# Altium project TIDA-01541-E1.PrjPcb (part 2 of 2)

## Sheet TIDA-01541-E1_MCU Interface.SchDoc: MCU Interface
size 431 x 279 mm; Date: Not shown in title block; ApprovedBy: Not shown in title block; CheckedBy: Not shown in title block; Author: Not shown in title block; CompanyName: Not shown in title block; DrawnBy: NN; Engineer: Not shown in title block; Organization: Not shown in title block; Address1: Not shown in title block; Address2: Not shown in title block; Address3: Not shown in title block; Address4: Not shown in title block; DocumentNumber: 1; Revision: Use project parameter SCH_Rev; SheetNumber: 5; SheetTotal: 6; PageSetup: Record=PageOptions¦CenterHorizontal=True¦CenterVertical=True¦PrintScale=1.00¦XCorrection=1.00¦YCorrection=1.00¦PrintKind=0¦BorderSize=5000000¦LeftOffset=0¦BottomOffset=0¦Orientation=2¦PaperLength=1000¦PaperWidth=1000¦Scale=100¦PaperSource=15¦PrintQuality=600¦MediaType=1¦DitherType=10¦PaperKind=Letter¦PrintScaleMode=1
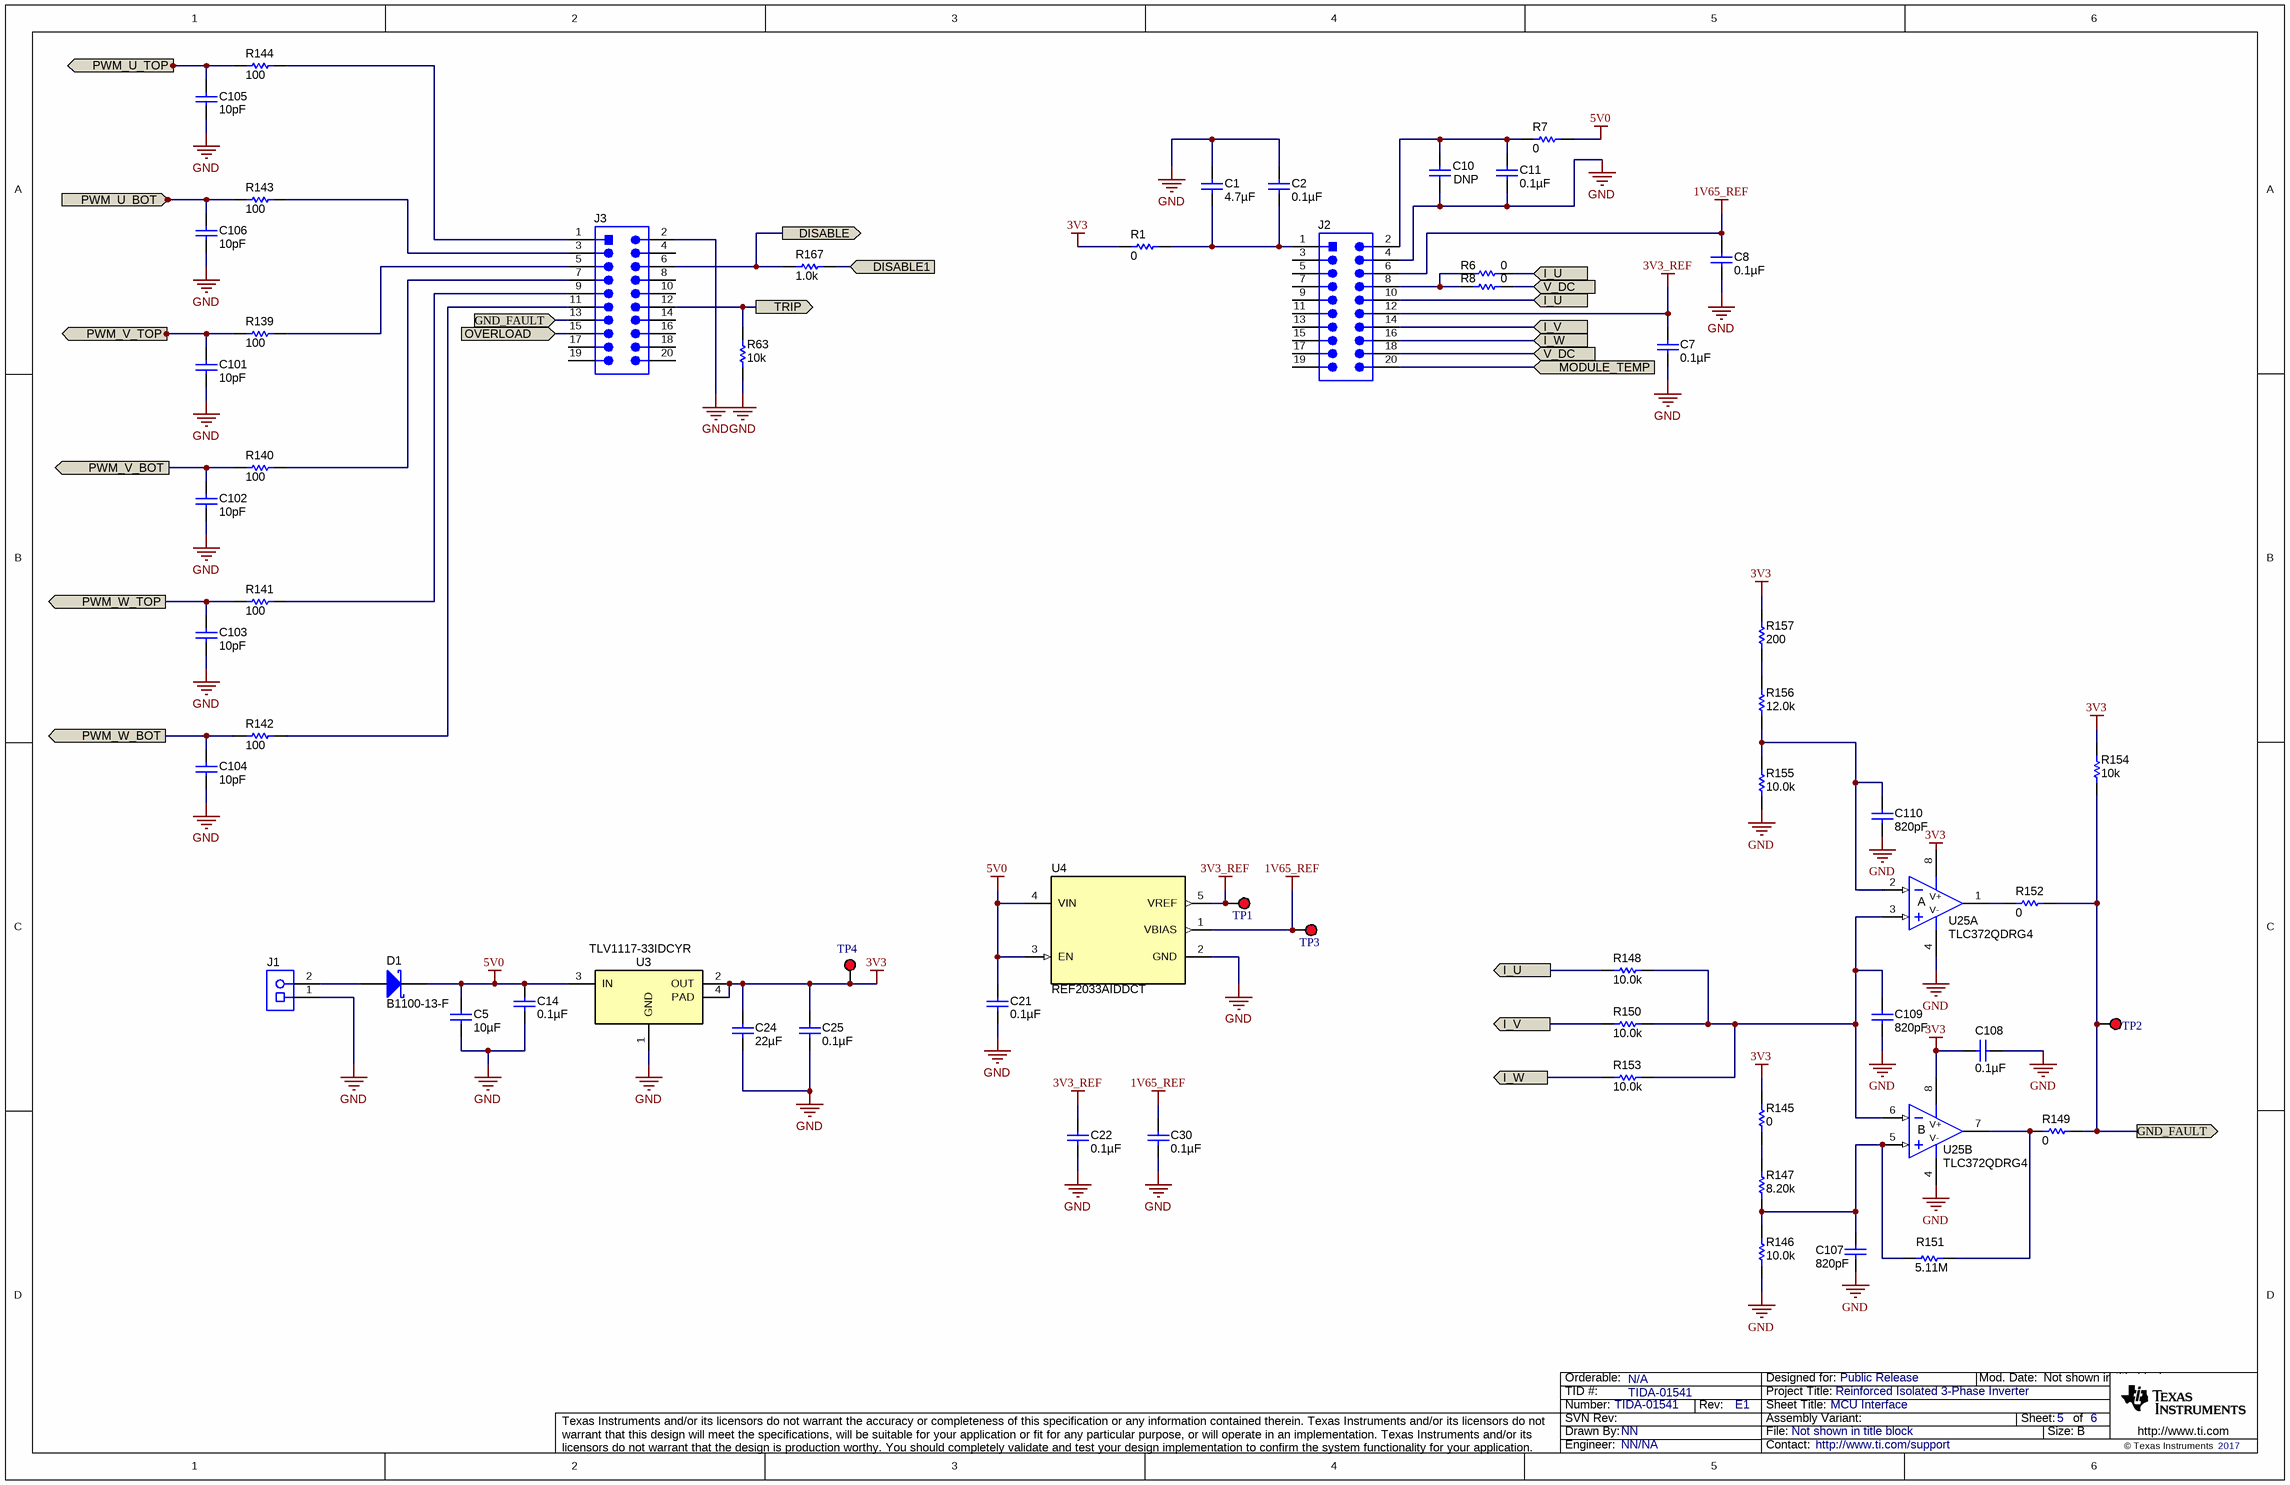
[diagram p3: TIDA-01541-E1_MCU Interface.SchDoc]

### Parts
C1  ValueDisplayed: 4.7µF  [0805_HV]  (hidden comment: C2012X5R1H475K125AB)
C2  ValueDisplayed: 0.1µF  [0603]  (hidden comment: GRM188R71H104KA93D)
C5  ValueDisplayed: 10µF  [1210_280]  (hidden comment: C3225X5R1H106K250AB)
C7  ValueDisplayed: 0.1µF  [0603]  (hidden comment: GRM188R71H104KA93D)
C8  ValueDisplayed: 0.1µF  [0603]  (hidden comment: GRM188R71H104KA93D)
C10  C2012X5R1H475K125AB  [0805_HV]  (value not drawn)
C11  ValueDisplayed: 0.1µF  [0603]  (hidden comment: GRM188R71H104KA93D)
C14  ValueDisplayed: 0.1µF  [0603]  (hidden comment: GRM188R71H104KA93D)
C21  ValueDisplayed: 0.1µF  [0603]  (hidden comment: GRM188R71H104KA93D)
C22  ValueDisplayed: 0.1µF  [0603]  (hidden comment: GRM188R71H104KA93D)
C24  ValueDisplayed: 22µF  [0805_HV]  (hidden comment: CL21A226MAQNNNE)
C25  ValueDisplayed: 0.1µF  [0603]  (hidden comment: GRM188R71H104KA93D)
C30  ValueDisplayed: 0.1µF  [0603]  (hidden comment: GRM188R71H104KA93D)
C101  ValueDisplayed: 10pF  [0603]  (hidden comment: GRM1885C1H100JA01D)
C102  ValueDisplayed: 10pF  [0603]  (hidden comment: GRM1885C1H100JA01D)
C103  ValueDisplayed: 10pF  [0603]  (hidden comment: GRM1885C1H100JA01D)
C104  ValueDisplayed: 10pF  [0603]  (hidden comment: GRM1885C1H100JA01D)
C105  ValueDisplayed: 10pF  [0603]  (hidden comment: GRM1885C1H100JA01D)
C106  ValueDisplayed: 10pF  [0603]  (hidden comment: GRM1885C1H100JA01D)
C107  ValueDisplayed: 820pF  [0603]  (hidden comment: GRM188R71H821KA01D)
C108  ValueDisplayed: 0.1µF  [0603]  (hidden comment: GRM188R71H104KA93D)
C109  ValueDisplayed: 820pF  [0603]  (hidden comment: GRM188R71H821KA01D)
C110  ValueDisplayed: 820pF  [0603]  (hidden comment: GRM188R71H821KA01D)
D1  B1100-13-F  [SMA]
J1  282834-2  [TEC_282834-2]  (value not drawn)
J2  TSW-110-07-G-D  [TSW-110-07-G-D]  (value not drawn)
J3  TSW-110-07-G-D  [TSW-110-07-G-D]  (value not drawn)
R1  ValueDisplayed: 0  [0805_HV]  (hidden comment: ERJ-6GEY0R00V)
R6  ValueDisplayed: 0  [0603]  (hidden comment: ERJ-3GEY0R00V)
R7  ValueDisplayed: 0  [0805_HV]  (hidden comment: ERJ-6GEY0R00V)
R8  ValueDisplayed: 0  [0603]  (hidden comment: ERJ-3GEY0R00V)
R63  ValueDisplayed: 10k  [0603]  (hidden comment: RC0603JR-0710KL)
R139  ValueDisplayed: 100  [0603]  (hidden comment: RC0603FR-07100RL)
R140  ValueDisplayed: 100  [0603]  (hidden comment: RC0603FR-07100RL)
R141  ValueDisplayed: 100  [0603]  (hidden comment: RC0603FR-07100RL)
R142  ValueDisplayed: 100  [0603]  (hidden comment: RC0603FR-07100RL)
R143  ValueDisplayed: 100  [0603]  (hidden comment: RC0603FR-07100RL)
R144  ValueDisplayed: 100  [0603]  (hidden comment: RC0603FR-07100RL)
R145  ValueDisplayed: 0  [0603]  (hidden comment: ERJ-3GEY0R00V)
R146  ValueDisplayed: 10.0k  [0603]  (hidden comment: PHT0603Y1002BGT200)
R147  ValueDisplayed: 8.20k  [0603]  (hidden comment: RG1608P-822-B-T5)
R148  ValueDisplayed: 10.0k  [0603]  (hidden comment: PHT0603Y1002BGT200)
R149  ValueDisplayed: 0  [0603]  (hidden comment: ERJ-3GEY0R00V)
R150  ValueDisplayed: 10.0k  [0603]  (hidden comment: PHT0603Y1002BGT200)
R151  ValueDisplayed: 5.11M  [0603]  (hidden comment: CRCW06035M11FKEA)
R152  ValueDisplayed: 0  [0603]  (hidden comment: ERJ-3GEY0R00V)
R153  ValueDisplayed: 10.0k  [0603]  (hidden comment: PHT0603Y1002BGT200)
R154  ValueDisplayed: 10k  [0603]  (hidden comment: RC0603JR-0710KL)
R155  ValueDisplayed: 10.0k  [0603]  (hidden comment: PHT0603Y1002BGT200)
R156  ValueDisplayed: 12.0k  [0603]  (hidden comment: RG1608P-123-B-T5)
R157  ValueDisplayed: 200  [0603]  (hidden comment: RG1608P-201-B-T5)
R167  ValueDisplayed: 1.0k  [0603]  (hidden comment: RC0603JR-071KL)
TP1  5000  [Keystone5000]  (value not drawn)
TP2  5000  [Keystone5000]  (value not drawn)
TP3  5000  [Keystone5000]  (value not drawn)
TP4  5000  [Keystone5000]  (value not drawn)
U3  TLV1117-33IDCYR  [DCY0003A_N]
U4  REF2033AIDDCT  [DDC0005A_N]
U25  TLC372QDRG4  [D0008A_N]  (parts A,B of 2)

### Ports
DISABLE1 (in), DISABLE (out), GND_FAULT (in), GND_FAULT (out), I_U, I_U (in), I_V, I_V (in), I_W, I_W (in), MODULE_TEMP (in), OVERLOAD (in), PWM_U_BOT (out), PWM_U_TOP (out), PWM_V_BOT (out), PWM_V_TOP (out), PWM_W_BOT (out), PWM_W_TOP (out), TRIP (out), V_DC (in)

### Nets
1V65_REF: C8.1 C30.1 J2.6 TP3.1 U4.1(VBIAS)
3V3: C24.1 C25.1 C108.2 R1.1 R145.1 R154.2 R157.1 TP4.1 U3.2(OUT) U3.4(PAD) U25.8(V+)
3V3_REF: C7.1 C22.1 J2.12 TP1.1 U4.5(VREF)
5V0: C5.1 C14.1 C21.1 D1.1(K) R7.2 U3.3(IN) U4.3(EN) U4.4(VIN)
GND: C1.1 C2.1 C5.2 C7.2 C8.2 C10.2 C11.2 C14.2 C21.2 C22.2 C24.2 C25.2 C30.2 C101.2 C102.2 C103.2 C104.2 C105.2 C106.2 C107.1 C108.1 C109.1 C110.1 J1.1 J2.4 J3.2 R63.1 R146.2 R155.2 U3.1(GND) U4.2(GND) U25.4(V-)
DISABLE: J3.6 R167.2 ; port DISABLE
DISABLE1: R167.1 ; port DISABLE1
GND_FAULT: J3.13 R149.2 R152.2 R154.1 TP2.1 ; port GND_FAULT
I_U: J2.10 R6.2 R148.1 ; port I_U
I_V: J2.14 R150.1 ; port I_V
I_W: J2.16 R153.1 ; port I_W
MODULE_TEMP: J2.20 ; port MODULE_TEMP
OVERLOAD: J3.15 ; port OVERLOAD
PWM_U_BOT: C106.1 R143.1 ; port PWM_U_BOT
PWM_U_TOP: C105.1 R144.1 ; port PWM_U_TOP
PWM_V_BOT: C102.1 R140.1 ; port PWM_V_BOT
PWM_V_TOP: C101.1 R139.1 ; port PWM_V_TOP
PWM_W_BOT: C104.1 R142.1 ; port PWM_W_BOT
PWM_W_TOP: C103.1 R141.1 ; port PWM_W_TOP
TRIP: J3.12 R63.2 ; port TRIP
V_DC: J2.18 R8.2 ; port V_DC
NetC1_2: C1.2 C2.2 J2.1 R1.2
NetC10_1: C10.1 C11.1 J2.2 R7.1
NetC107_2: C107.2 R146.1 R147.2 R151.1 U25.5(IN+)
NetC109_2: C109.2 R148.2 R150.2 R153.2 U25.3(IN+) U25.6(IN-)
NetC110_2: C110.2 R155.1 R156.2 U25.2(IN-)
NetD1_2: D1.2(A) J1.2
NetJ2_8: J2.8 R6.1 R8.1
NetJ3_1: J3.1 R144.2
NetJ3_3: J3.3 R143.2
NetJ3_5: J3.5 R139.2
NetJ3_7: J3.7 R140.2
NetJ3_9: J3.9 R141.2
NetJ3_11: J3.11 R142.2
NetR145_2: R145.2 R147.1
NetR149_1: R149.1 R151.2 U25.7(OUT)
NetR152_1: R152.1 U25.1(OUT)
NetR156_1: R156.1 R157.2

Not connected (* = marked no-connect by the designer): J2 3 5 7 9 11 13 15 17 19; J3 4 8 10 14 16 17 18 19 20

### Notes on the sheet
- Labels drawn without touching a wire or pin: 3V3

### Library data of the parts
C1 = C2012X5R1H475K125AB: CAP, CERM, 4.7 µF, 50 V, +/- 10%, X5R, 0805; Manufacturer: TDK; Polarized: N; CompType: Capacitor; Value: 4.7uF; U/M: EA; Cap_F: 0.0000047; Tolerance_%: 10; Value1: Unknown; VDC_V: 50; Value2: 50V; TaMin_C: -55; TaMax_C: 85; Cap_Case: 0805; AEC Category: Q200
C2 C7 C8 C11 C14 C21 C22 C25 C30 = GRM188R71H104KA93D: CAP, CERM, 0.1 µF, 50 V, +/- 10%, X7R, 0603; Manufacturer: MuRata; Polarized: N; CompType: Capacitor; Value: 0.1uF; U/M: EA; Cap_F: 0.0000001; Tolerance_%: 10; Value1: Unknown; VDC_V: 50; Value2: 50V; TaMin_C: -55; TaMax_C: 125; AEC Category: Q200; SizeArea_mm2: 1.28; SizeAreaWB_mm2: 4.68; SizeX_mm: 1.6; SizeY_mm: 0.8; SizeZ_mm: 1
C5 = C3225X5R1H106K250AB: CAP, CERM, 10 µF, 50 V, +/- 10%, X5R, 1210; Manufacturer: TDK; Polarized: N; CompType: Capacitor; Value: 10uF; U/M: EA; Cap_F: 0.00001; Tolerance_%: 10; Value1: Unknown; VDC_V: 50; Value2: 50V; TaMin_C: -55; TaMax_C: 85; Cap_Case: 1210; AEC Category: Q200
C10 = C2012X5R1H475K125AB: CAP, CERM, 4.7 µF, 50 V, +/- 10%, X5R, 0805; Manufacturer: TDK; Polarized: N; CompType: Capacitor; Value: 4.7uF; ValueDisplayed: 4.7µF; U/M: EA; Cap_F: 0.0000047; Tolerance_%: 10; Value1: Unknown; VDC_V: 50; Value2: 50V; TaMin_C: -55; TaMax_C: 85; Cap_Case: 0805; AEC Category: Q200
C24 = CL21A226MAQNNNE: CAP, CERM, 22 µF, 25 V, +/- 20%, X5R, 0805; Manufacturer: Samsung Electro-Mechanics; Polarized: N; CompType: Capacitor; Value: 22uF; U/M: EA; Cap_F: 0.000022; Tolerance_%: 20; Value1: Unknown; VDC_V: 25; Value2: 25V; TaMin_C: -55; TaMax_C: 85; Cap_Case: 0805; AEC Category: Q200; SizeArea_mm2: 2.5; SizeAreaWB_mm2: 6.75; SizeX_mm: 2; SizeY_mm: 1.25; SizeZ_mm: 1.45
C101-C106 = GRM1885C1H100JA01D: CAP, CERM, 10 pF, 50 V, +/- 5%, C0G/NP0, 0603; Manufacturer: MuRata; Polarized: N; CompType: Capacitor; Value: 10pF; U/M: EA; Cap_F: 0.00000000001; Tolerance_%: 5; Value1: Unknown; VDC_V: 50; Value2: 50V; TaMin_C: -55; TaMax_C: 125; AEC Category: Q200; SizeArea_mm2: 1.28; SizeAreaWB_mm2: 4.68; SizeX_mm: 1.6; SizeY_mm: 0.8; SizeZ_mm: 1
C107 C109 C110 = GRM188R71H821KA01D: CAP, CERM, 820 pF, 50 V, +/- 10%, X7R, 0603; Manufacturer: MuRata; Polarized: N; CompType: Capacitor; Value: 820pF; U/M: EA; Cap_F: 0.00000000082; Tolerance_%: 10; Value1: Unknown; VDC_V: 50; Value2: 50V; TaMin_C: -55; TaMax_C: 125
C108 = GRM188R71H104KA93D: CAP, CERM, 0.1 µF, 50 V, +/- 10%, X7R, 0603; Manufacturer: MuRata; Polarized: N; CompType: Capacitor; Value: 0.1uF; U/M: EA; Cap_F: 0.0000001; Tolerance_%: 10; Value1: Unknown; VDC_V: 50; Value2: 50V; TaMin_C: -55; TaMax_C: 125
D1 = B1100-13-F: Diode, Schottky, 100 V, 1 A, SMA; Manufacturer: Diodes Inc.; U/M: EA; Vf_V: 0.79; Value: 100V; Value1: 1A; Value2: 0.79V; Io_A: 1; Vr_V: 100; TJmax_C: 150; RJC_CperW: 25; AEC Category: Q101
J1 = 282834-2: Terminal Block, 2x1, 2.54mm, TH; Manufacturer: TE Connectivity; SymbolCreator: a0412235
J2 J3 = TSW-110-07-G-D: Header, 100mil, 10x2, Gold, TH; Manufacturer: Samtec; SymbolCreator: a0412235; Pitch_mm: 2.54; Gender: Male; Shrouded: N; Row_Count: 2; Current_A: 6.3; Voltage_V: 550; Cert_CSA: Y
R1 R7 = ERJ-6GEY0R00V: RES, 0, 5%, 0.125 W, 0805; Manufacturer: Panasonic; CompType: Resistor; Value: 0; Value_Code: 0000; Tolerance_%: 5; Power_W: 0.125; Value2: 0.125W; VDC_V: 150; TempCo: 600 ppm/C; EIA_Code: E24; U/M: EA; AEC Category: Q200; SizeArea_mm2: 2.5; SizeX_mm: 2; SizeY_mm: 1.25; SizeZ_mm: 1.45
R6 R8 = ERJ-3GEY0R00V: RES, 0, 5%, 0.1 W, 0603; Manufacturer: Panasonic; CompType: Resistor; Value: 0; Value_Code: 0000; Tolerance_%: 5; Power_W: 0.1; Value2: 0.1W; VDC_V: 50; TempCo: 600 ppm/C; EIA_Code: E24; U/M: EA; AEC Category: Q200; SizeArea_mm2: 1.28; SizeX_mm: 1.6; SizeY_mm: 0.8; SizeZ_mm: 1
R63 = RC0603JR-0710KL: RES, 10 k, 5%, 0.1 W, 0603; Manufacturer: Yageo America; CompType: Resistor; Value: 10k; Res_ohm: 10000; Value_Code: 10k0; Tolerance_%: 5; Power_W: 0.1; Value2: 0.1W; VDC_V: 50; TempCo: 100 ppm/C; EIA_Code: E24; U/M: EA; AEC Category: Q200; SizeArea_mm2: 1.28; SizeX_mm: 1.6; SizeY_mm: 0.8; SizeZ_mm: 1
R139-R144 = RC0603FR-07100RL: RES, 100, 1%, 0.1 W, 0603; Manufacturer: Yageo America; CompType: Resistor; Value: 100; Value_Code: 100R; Tolerance_%: 1; Power_W: 0.1; Value2: 0.1W; VDC_V: 150; TempCo: 200 ppm/C; EIA_Code: E96; U/M: EA; AEC Category: Q200; SizeArea_mm2: 1.28; SizeX_mm: 1.6; SizeY_mm: 0.8
R145 R149 R152 = ERJ-3GEY0R00V: RES, 0, 5%, 0.1 W, 0603; Manufacturer: Panasonic; CompType: Resistor; Value: 0; Value_Code: 0000; Tolerance_%: 5; Power_W: 0.1; Value2: 0.1W; VDC_V: 50; TempCo: 600 ppm/C; EIA_Code: E24; U/M: EA; SizeArea_mm2: 1.28; SizeX_mm: 1.6; SizeY_mm: 0.8; SizeZ_mm: 1; AEC Category: Q200
R146 R148 R150 R153 = PHT0603Y1002BGT200: RES, 10.0 k, 0.1%, 0.0375 W, 0603; Manufacturer: Vishay Sfernice; CompType: Resistor; Value: 10.0k; Res_ohm: 10000; Value_Code: 10k0; Tolerance_%: 0.1; Power_W: 0.0375; VDC_V: 75; TempCo: 15 ppm/C; EIA_Code: E192; U/M: EA; AEC Category: Q200
R147 = RG1608P-822-B-T5: RES, 8.20 k, 0.1%, 0.1 W, 0603; Manufacturer: Susumu Co Ltd; CompType: Resistor; Value: 8.20k; Res_ohm: 8200; Value_Code: 8k20; Tolerance_%: 0.1; Value2: 0.1W; VDC_V: 75; TempCo: 25 ppm/C; U/M: EA; AEC Category: Q200; SizeArea_mm2: 1.28; SizeX_mm: 1.6; SizeY_mm: 0.8; SizeZ_mm: 1
R151 = CRCW06035M11FKEA: RES, 5.11 M, 1%, 0.1 W, 0603; Manufacturer: Vishay-Dale; CompType: Resistor; Value: 5.11Meg; Res_ohm: 5110000; Value_Code: 5M11; Tolerance_%: 1; Power_W: 0.1; Value2: 0.1W; VDC_V: 75; TempCo: 100 ppm/C; EIA_Code: E96; U/M: EA
R154 = RC0603JR-0710KL: RES, 10 k, 5%, 0.1 W, 0603; Manufacturer: Yageo America; CompType: Resistor; Value: 10k; Res_ohm: 10000; Value_Code: 10k0; Tolerance_%: 5; Power_W: 0.1; Value2: 0.1W; VDC_V: 50; TempCo: 100 ppm/C; EIA_Code: E24; U/M: EA; SizeArea_mm2: 1.28; SizeX_mm: 1.6; SizeY_mm: 0.8; SizeZ_mm: 1; AEC Category: Q200
R155 = PHT0603Y1002BGT200: RES, 10.0 k, 0.1%, 0.0375 W, 0603; Manufacturer: Vishay Sfernice; CompType: Resistor; Value: 10.0k; Res_ohm: 10000; Value_Code: 10k0; Tolerance_%: 0.1; Power_W: 0.0375; VDC_V: 75; TempCo: 15 ppm/C; EIA_Code: E192; U/M: EA; AEC Category: Q200; SizeArea_mm2: 1.28; SizeX_mm: 1.6; SizeY_mm: 0.8; SizeZ_mm: 1
R156 = RG1608P-123-B-T5: RES, 12.0 k, 0.1%, 0.1 W, 0603; Manufacturer: Susumu Co Ltd; CompType: Resistor; Value: 12.0k; Res_ohm: 12000; Value_Code: 12k0; Tolerance_%: 0.1; Value2: 0.1W; VDC_V: 75; TempCo: 25 ppm/C; EIA_Code: E192; U/M: EA; AEC Category: Q200; SizeArea_mm2: 1.28; SizeX_mm: 1.6; SizeY_mm: 0.8; SizeZ_mm: 1
R157 = RG1608P-201-B-T5: RES, 200, 0.1%, 0.1 W, 0603; Manufacturer: Susumu Co Ltd; CompType: Resistor; Value: 200; Value_Code: 200R; Tolerance_%: 0.1; Value2: 0.1W; VDC_V: 75; TempCo: 25 ppm/C; EIA_Code: E192; U/M: EA; SizeArea_mm2: 1.28; SizeX_mm: 1.6; SizeY_mm: 0.8; SizeZ_mm: 1; AEC Category: Q200
R167 = RC0603JR-071KL: RES, 1.0 k, 5%, 0.1 W, 0603; Manufacturer: Yageo America; CompType: Resistor; Value: 1.0k; Res_ohm: 1000; Value_Code: 1k00; Tolerance_%: 5; Power_W: 0.1; Value2: 0.1W; VDC_V: 50; TempCo: 100 ppm/C; EIA_Code: E24; U/M: EA; SizeArea_mm2: 1.28; SizeX_mm: 1.6; SizeY_mm: 0.8; SizeZ_mm: 1; AEC Category: Q200
TP1-TP4 = 5000: Test Point, Miniature, Red, TH; Manufacturer: Keystone; CompType: Test Point Loop; ContactFinish: Silver
U3 = TLV1117-33IDCY: FIXED LOW-DROPOUT VOLTAGE REGULATOR, DCY0003A; Manufacturer: Texas Instruments; SymbolCreator: a0411947; CompType: IC; U/M: EA
U4 = REF2033AIDDCR: Low-Drift, Low-Power, Dual-Output, VREF and VREF / 2 Voltage References, DDC0005A; Manufacturer: Texas Instruments; SymbolCreator: a0799628; CompType: IC; U/M: EA
U25 = TLC372QDR: LinCMOS Dual Differential Comparators, D0008A; Manufacturer: Texas Instruments; SymbolCreator: a0411947; CompType: IC; U/M: EA

## Sheet TIDA-01541-E1_EVM_Hardware.SchDoc: Hardware
size 431 x 279 mm; Date: Not shown in title block; ApprovedBy: Not shown in title block; CheckedBy: Not shown in title block; Author: Not shown in title block; CompanyName: Not shown in title block; DrawnBy: NN; Engineer: Not shown in title block; Organization: Not shown in title block; Address1: Not shown in title block; Address2: Not shown in title block; Address3: Not shown in title block; Address4: Not shown in title block; DocumentNumber: 1; Revision: Use project parameter SCH_Rev; SheetNumber: 6; SheetTotal: 6; PageSetup: Record=PageOptions¦CenterHorizontal=True¦CenterVertical=True¦PrintScale=1.00¦XCorrection=1.00¦YCorrection=1.00¦PrintKind=0¦BorderSize=5000000¦LeftOffset=0¦BottomOffset=0¦Orientation=2¦PaperLength=1000¦PaperWidth=1000¦Scale=100¦PaperSource=15¦PrintQuality=600¦MediaType=1¦DitherType=10¦PaperKind=Letter¦PrintScaleMode=1
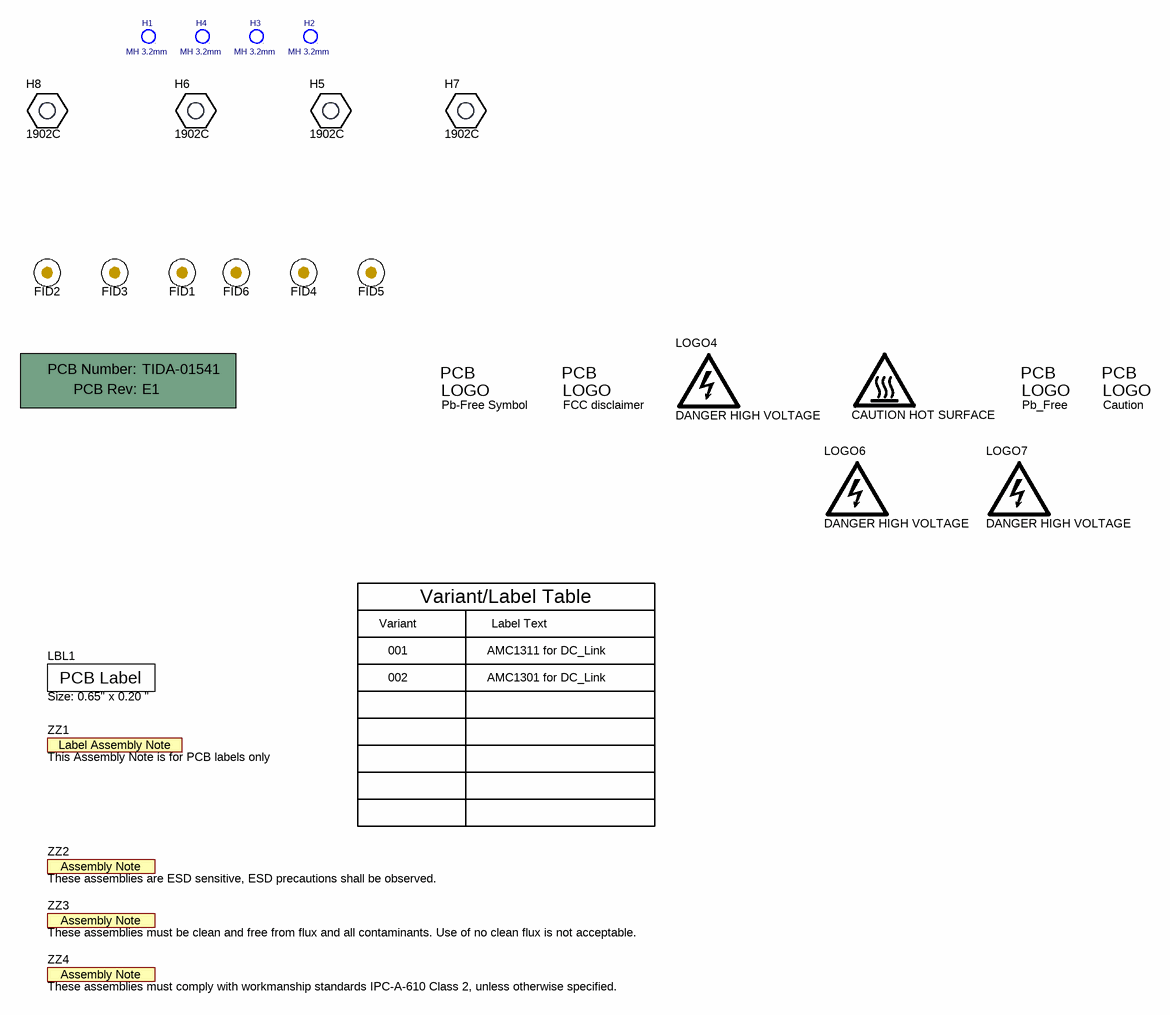
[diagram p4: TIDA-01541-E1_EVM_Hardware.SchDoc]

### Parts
!PCB1  Printed Circuit Board  (value not drawn)  (mechanical)
Caution  CAUTION.  READ USER GUIDE BEFORE USE  [IEC_Caution_Medium]  (value not drawn)  (no BOM)
CAUTION_HOT_SURFACE  CAUTION HOT SURFACE  [IEC_HotSurface_Medium]  (value not drawn)  (no BOM)
FID1  Fiducial  [Fiducial10-20]  (value not drawn)
FID2  Fiducial  [Fiducial10-20]  (value not drawn)
FID3  Fiducial  [Fiducial10-20]  (value not drawn)
FID4  Fiducial  [Fiducial10-20]  (value not drawn)
FID5  Fiducial  [Fiducial10-20]  (value not drawn)
FID6  Fiducial  [Fiducial10-20]  (value not drawn)
H1  MH 3.2mm  [MH3.2_H5_W6_KO8_STARHEAD]
H2  MH 3.2mm  [MH3.2_H5_W6_KO8_STARHEAD]
H3  MH 3.2mm  [MH3.2_H5_W6_KO8_STARHEAD]
H4  MH 3.2mm  [MH3.2_H5_W6_KO8_STARHEAD]
H5  1902C  [Keystone_1902C]
H6  1902C  [Keystone_1902C]
H7  1902C  [Keystone_1902C]
H8  1902C  [Keystone_1902C]
LBL1  Size: 0.65" x 0.20 "  [Label_650x200]
Logo2  Pb-Free Symbol  [Pb-Free_Overlay_Small]  (no BOM)
Logo3  FCC disclaimer  [FCC_disclaimer]  (no BOM)
LOGO4  DANGER HIGH VOLTAGE  [IEC_HighVoltage_medium]  (no BOM)
LOGO6  DANGER HIGH VOLTAGE  [IEC_HighVoltage_medium]  (no BOM)
LOGO7  DANGER HIGH VOLTAGE  [IEC_HighVoltage_medium]  (no BOM)
Pb_Free  ESD Susceptible  [ESD_Overlay_Medium]  (value not drawn)  (no BOM)
ZZ1  This Assembly Note is for PCB labels only  [AssemblyNoteLabel]  (no BOM)
ZZ2  These assemblies are ESD sensitive, ESD precautions shall be observed.  [AssemblyNote]  (no BOM)
ZZ3  These assemblies must be clean and free from flux and all contaminants. Use of no clean flux is not acceptable.  [AssemblyNote]  (no BOM)
ZZ4  These assemblies must comply with workmanship standards IPC-A-610 Class 2, unless otherwise specified.  [AssemblyNote]  (no BOM)

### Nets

Not connected (* = marked no-connect by the designer): H1 1; H2 1; H3 1; H4 1

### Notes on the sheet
- Variant
- Variant/Label Table
- Label Text
- 001
- 002
- AMC1311 for DC_Link
- AMC1301 for DC_Link

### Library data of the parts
!PCB1 = PCB: Manufacturer: Any; PartNumber: TIDA-01541; SymbolCreator: a0412235
Caution = IEC_Caution: IEC 61010-1 Caution Warning; SymbolCreator: a0412235
CAUTION_HOT_SURFACE = IEC_HotSurface: IEC 61010-1 Hot Surface Warning; SymbolCreator: a0412235
FID1-FID6 = Fiducial: Fiducial mark.  There is nothing to buy or mount.; SymbolCreator: codlsc
H1-H4 = MH 3_0.5MM: Mountin hole, NPTH Drill 3.2mm
H5-H8 = 1902C: Standoff, Hex, 0.5"L #4-40 Nylon; Manufacturer: Keystone; CompType: Hardware
LBL1 = THT-14-423-10: Thermal Transfer Printable Labels, 0.650" W x 0.200" H - 10,000 per roll; Manufacturer: Brady; SymbolCreator: a0412235; CompType: Label
Logo2 = Pb-Free: SymbolCreator: a0412235
Logo3 = FCC_disclaimer: SymbolCreator: codlsc
LOGO4 LOGO6 LOGO7 = IEC_HighVoltage: IEC 61010-1 High Voltage Warning; SymbolCreator: a0412235
Pb_Free = ESD_Susceptible: ESD Susceptible Symbol; SymbolCreator: a0412235
ZZ1 = AssemblyNoteLabel: SymbolCreator: a0412235
ZZ2-ZZ4 = AssemblyNote: SymbolCreator: codlsc

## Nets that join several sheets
1V65_REF: TIDA-01541-E1_Current sense (6 pins), TIDA-01541-E1_DC BUS and TEMP Sense (C3.2 C38.2 R2.1 R41.1), TIDA-01541-E1_MCU Interface (5 pins)
3V3: TIDA-01541-E1_Gate driver and Module (14 pins), TIDA-01541-E1_Current sense (28 pins), TIDA-01541-E1_DC BUS and TEMP Sense (10 pins), TIDA-01541-E1_MCU Interface (11 pins)
GND: TIDA-01541-E1_Gate driver and Module (19 pins), TIDA-01541-E1_Current sense (42 pins), TIDA-01541-E1_DC BUS and TEMP Sense (18 pins), TIDA-01541-E1_MCU Interface (32 pins)
3V3_VDC: TIDA-01541-E1_Gate driver and Module (R106.1), TIDA-01541-E1_DC BUS and TEMP Sense (9 pins)
+16V_GPS: TIDA-01541-E1_Gate driver and Module (14 pins), TIDA-01541-E1_DC BUS and TEMP Sense (R110.1)
DISABLE: TIDA-01541-E1_Gate driver and Module (R164.1 R165.1 R166.1), TIDA-01541-E1_MCU Interface (J3.6 R167.2)
DISABLE1: TIDA-01541-E1_Gate driver and Module (C46.1 R43.2), TIDA-01541-E1_MCU Interface (R167.1)
GND_FAULT: TIDA-01541-E1_Gate driver and Module (U8.1), TIDA-01541-E1_MCU Interface (5 pins)
I_U: TIDA-01541-E1_Current sense (C12.1 R13.2), TIDA-01541-E1_MCU Interface (J2.10 R6.2 R148.1)
I_V: TIDA-01541-E1_Current sense (C19.1 R17.2), TIDA-01541-E1_MCU Interface (J2.14 R150.1)
I_W: TIDA-01541-E1_Current sense (C17.1 R16.2), TIDA-01541-E1_MCU Interface (J2.16 R153.1)
MODULE_TEMP: TIDA-01541-E1_DC BUS and TEMP Sense (C20.1 R19.2), TIDA-01541-E1_MCU Interface (J2.20)
NTC: TIDA-01541-E1_Gate driver and Module (R106.2 U24.17), TIDA-01541-E1_DC BUS and TEMP Sense (R93.1)
OVERLOAD: TIDA-01541-E1_Gate driver and Module (U8.6), TIDA-01541-E1_Current sense (7 pins), TIDA-01541-E1_MCU Interface (J3.15)
PWM_U_BOT: TIDA-01541-E1_Gate driver and Module (U19.2), TIDA-01541-E1_MCU Interface (C106.1 R143.1)
PWM_U_TOP: TIDA-01541-E1_Gate driver and Module (U19.1), TIDA-01541-E1_MCU Interface (C105.1 R144.1)
PWM_V_BOT: TIDA-01541-E1_Gate driver and Module (U17.2), TIDA-01541-E1_MCU Interface (C102.1 R140.1)
PWM_V_TOP: TIDA-01541-E1_Gate driver and Module (U17.1), TIDA-01541-E1_MCU Interface (C101.1 R139.1)
PWM_W_BOT: TIDA-01541-E1_Gate driver and Module (U18.2), TIDA-01541-E1_MCU Interface (C104.1 R142.1)
PWM_W_TOP: TIDA-01541-E1_Gate driver and Module (U18.1), TIDA-01541-E1_MCU Interface (C103.1 R141.1)
TRIP: TIDA-01541-E1_Gate driver and Module (U8.3), TIDA-01541-E1_MCU Interface (J3.12 R63.2)
U_PHASE: TIDA-01541-E1_Gate driver and Module (J14.3 R118.1), TIDA-01541-E1_Current sense (R86.1)
U_TOP_REF: TIDA-01541-E1_Gate driver and Module (10 pins), TIDA-01541-E1_Current sense (6 pins)
V_DC: TIDA-01541-E1_DC BUS and TEMP Sense (C9.1 R12.2), TIDA-01541-E1_MCU Interface (J2.18 R8.2)
V_PHASE: TIDA-01541-E1_Gate driver and Module (J14.2 R119.2), TIDA-01541-E1_Current sense (R88.1)
V_TOP_REF: TIDA-01541-E1_Gate driver and Module (10 pins), TIDA-01541-E1_Current sense (6 pins)
VCC_U: TIDA-01541-E1_Gate driver and Module (5 pins), TIDA-01541-E1_Current sense (R72.1)
VCC_V: TIDA-01541-E1_Gate driver and Module (5 pins), TIDA-01541-E1_Current sense (R73.1)
VCC_W: TIDA-01541-E1_Gate driver and Module (5 pins), TIDA-01541-E1_Current sense (R74.1)
VDC+: TIDA-01541-E1_Gate driver and Module (8 pins), TIDA-01541-E1_DC BUS and TEMP Sense (D10.1 R122.2)
VDC-: TIDA-01541-E1_Gate driver and Module (11 pins), TIDA-01541-E1_DC BUS and TEMP Sense (13 pins)
W_PHASE: TIDA-01541-E1_Gate driver and Module (J14.1 R120.2), TIDA-01541-E1_Current sense (R80.1)
W_TOP_REF: TIDA-01541-E1_Gate driver and Module (10 pins), TIDA-01541-E1_Current sense (6 pins)

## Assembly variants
001: not fitted C10 C11 C16 C33 C42 C94 D10 D11 J5 J6 J7 R2 R6 R7 R8 R22 R24 R38 R39 R41 R46 R64 R81 R90 R108; alternate parts R109 -> RC0603FR-0711KL, R107 -> ERJ-3GEY0R00V, R18 -> RC0603FR-0715KL, R91 -> ERJ-3GEY0R00V, R45 -> RC0603FR-0715KL, R106 -> RC0603FR-0715KL
002: not fitted C10 C11 C16 C33 C42 D10 D11 J5 J6 J7 R3 R6 R7 R8 R22 R24 R38 R39 R42 R46 R64 R108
